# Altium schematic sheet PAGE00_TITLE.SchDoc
size 254 x 254 mm; SheetNumber: 1; SheetTotal: 28
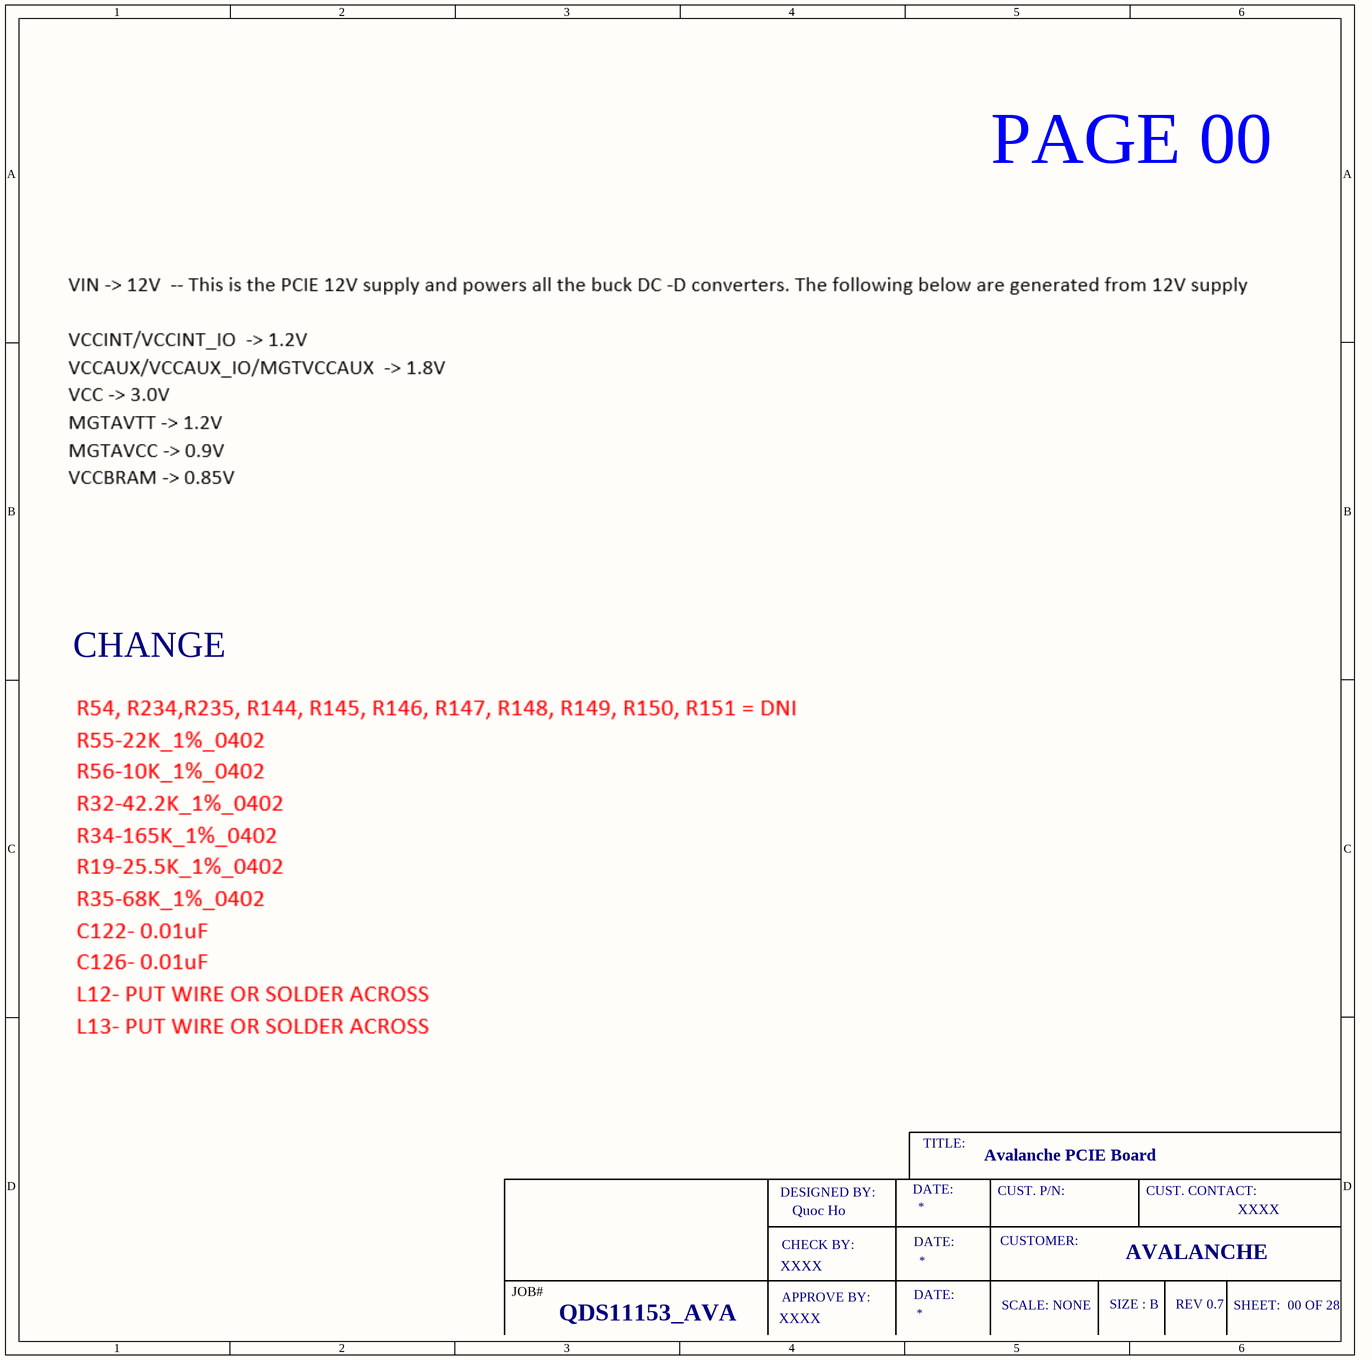
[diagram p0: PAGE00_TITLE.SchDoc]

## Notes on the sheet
- PAGE 00
- CHANGE
- TITLE:
- Avalanche PCIE Board
- DESIGNED BY:
- CHECK BY:
- Quoc Ho
- DATE:
- CUST. P/N:
- CUSTOMER:
- CUST. CONTACT:
- XXXX
- JOB#
- APPROVE BY:
- SCALE: NONE
- SIZE : B
- AVALANCHE
- REV 0.7
- SHEET:  00 OF 28
- QDS11153_AVA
